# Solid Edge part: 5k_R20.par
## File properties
Author: Türk
Template: Iso Part.par
Last saved by: Türk
Revision: 6
Application: Solid Edge
Accuracy: 0,990
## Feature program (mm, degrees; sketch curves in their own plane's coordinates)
pattern "PatternOccurrence_6"  XOffset = 14.4 deg
pattern "PatternOccurrence_7"  XCount = 25; XOffset = 14.4 deg
pattern "PatternOccurrence_8"  XOffset = 12 deg
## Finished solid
Body 1: solid body, 214 faces, 632 edges, 420 vertices.
  Faces by surface: cylinder 111, plane 103
  Edges by curve: line 410, circle 222
Bounding box of the edges (mm): 47.887 x 35.000 x 47.968, from (-23.8867, -5, -23.9822) to (24, 30, 23.9858).
Cylindrical faces by radius (mm): R1.25 x30, R14 x1, R15 x30, R20 x25, R24 x25
Planar faces by outward normal: +y 1, -y 2, oblique 100
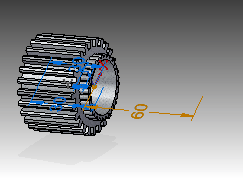
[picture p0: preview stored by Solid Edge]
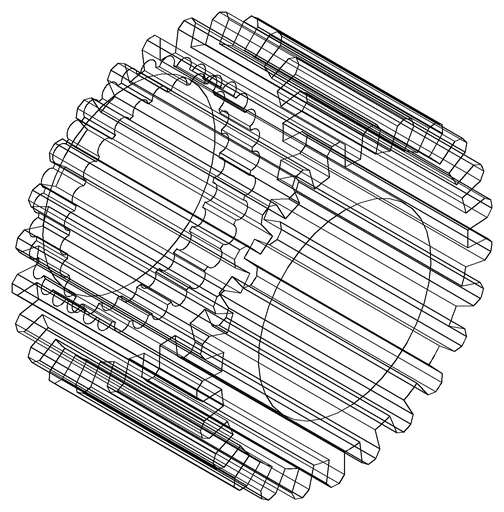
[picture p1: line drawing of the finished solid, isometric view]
